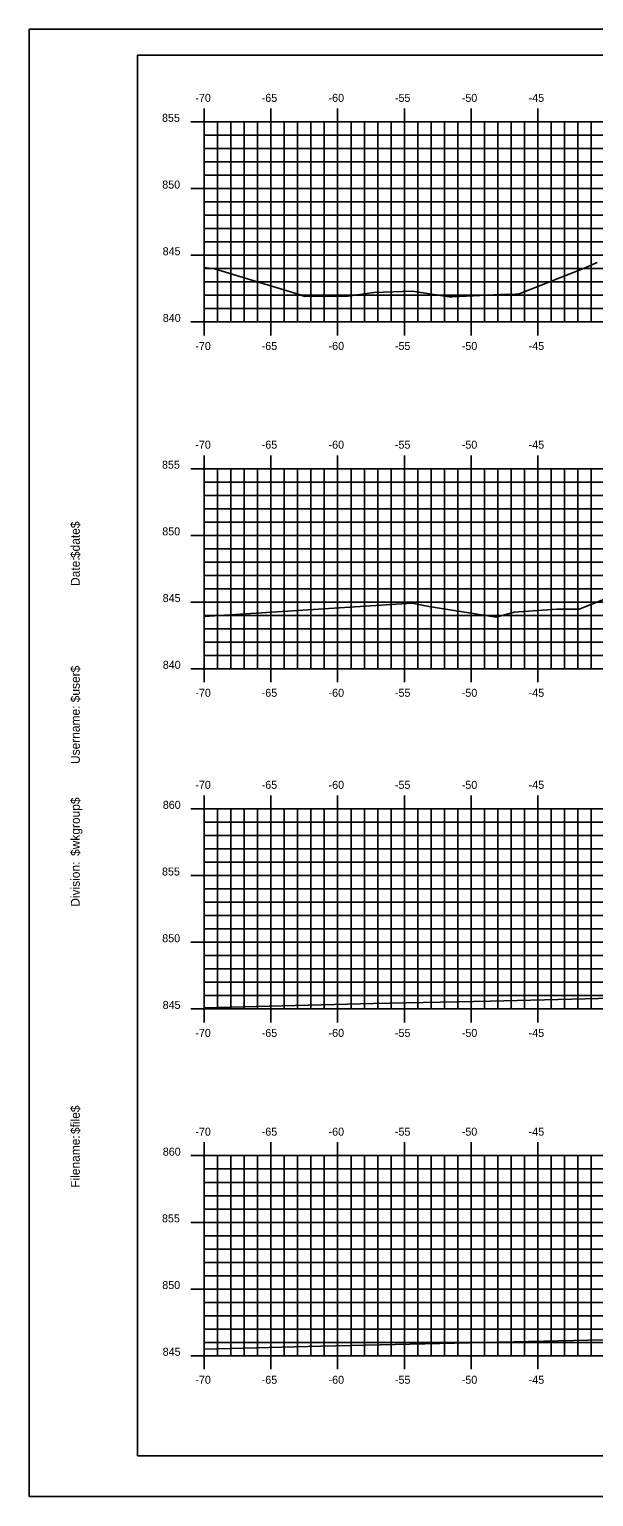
# Model space of a CAD drawing. Extents: x 2194004 to 2194525, y 863888 to 863998.
# Drawn here: x 2194171.9 to 2194214.2, y 863888.4 to 863998.4 of the extents above; entities that cross this region are included whole.
import ezdxf

# ---------------------------------------------------------------- set-up
doc = ezdxf.new("R2010")
doc.units = 0
for name, color, linetype in [('BORDER', 7, 'Continuous'), ('H_V ANNOTATION', 7, 'Continuous'), ('MAJOR', 7, 'Continuous'), ('MINOR', 7, 'Continuous'), ('PLOT BOUNDARY', 7, 'Continuous'), ('S_Roadway_Centerline', 7, 'Continuous')]:
    doc.layers.add(name, color=color, linetype=linetype)

msp = doc.modelspace()

# ---------------------------------------------------------------- linework, layer by layer
at = {"layer": 'BORDER'}
msp.add_lwpolyline([(2194179.99, 863891.45), (2194339.99, 863891.45), (2194339.99, 863996.45), (2194179.99, 863996.45)], close=True, dxfattribs=at)
at = {"layer": 'MAJOR'}
for p, q in [((2194184.99, 863992.45), (2194184.99, 863991.45)), ((2194189.99, 863992.45), (2194189.99, 863991.45)), ((2194194.99, 863992.45), (2194194.99, 863991.45)), ((2194199.99, 863992.45), (2194199.99, 863991.45)), ((2194204.99, 863992.45), (2194204.99, 863991.45)), ((2194209.99, 863992.45), (2194209.99, 863991.45)), ((2194183.98, 863991.45), (2194184.99, 863991.45)), ((2194184.99, 863991.45), (2194324.99, 863991.45)), ((2194184.99, 863976.45), (2194184.99, 863991.45)), ((2194184.99, 863976.45), (2194184.99, 863991.45)), ((2194189.99, 863976.45), (2194189.99, 863991.45)), ((2194194.99, 863976.45), (2194194.99, 863991.45)), ((2194199.99, 863976.45), (2194199.99, 863991.45)), ((2194204.99, 863976.45), (2194204.99, 863991.45)), ((2194209.99, 863976.45), (2194209.99, 863991.45)), ((2194183.98, 863986.45), (2194184.99, 863986.45)), ((2194184.99, 863986.45), (2194324.99, 863986.45)), ((2194183.98, 863981.45), (2194184.99, 863981.45)), ((2194184.99, 863981.45), (2194324.99, 863981.45)), ((2194183.98, 863976.45), (2194184.99, 863976.45)), ((2194184.99, 863976.45), (2194324.99, 863976.45)), ((2194184.99, 863975.44), (2194184.99, 863976.45)), ((2194189.99, 863975.44), (2194189.99, 863976.45)), ((2194194.99, 863975.44), (2194194.99, 863976.45)), ((2194199.99, 863975.44), (2194199.99, 863976.45)), ((2194204.99, 863975.44), (2194204.99, 863976.45)), ((2194209.99, 863975.44), (2194209.99, 863976.45)), ((2194184.99, 863966.45), (2194184.99, 863965.45)), ((2194189.99, 863966.45), (2194189.99, 863965.45)), ((2194194.99, 863966.45), (2194194.99, 863965.45)), ((2194199.99, 863966.45), (2194199.99, 863965.45)), ((2194204.99, 863966.45), (2194204.99, 863965.45)), ((2194209.99, 863966.45), (2194209.99, 863965.45)), ((2194183.98, 863965.45), (2194184.99, 863965.45)), ((2194184.99, 863965.45), (2194324.99, 863965.45)), ((2194184.99, 863950.45), (2194184.99, 863965.45)), ((2194184.99, 863950.45), (2194184.99, 863965.45)), ((2194189.99, 863950.45), (2194189.99, 863965.45)), ((2194194.99, 863950.45), (2194194.99, 863965.45)), ((2194199.99, 863950.45), (2194199.99, 863965.45)), ((2194204.99, 863950.45), (2194204.99, 863965.45)), ((2194209.99, 863950.45), (2194209.99, 863965.45)), ((2194183.98, 863960.45), (2194184.99, 863960.45)), ((2194184.99, 863960.45), (2194324.99, 863960.45)), ((2194183.98, 863955.45), (2194184.99, 863955.45)), ((2194184.99, 863955.45), (2194324.99, 863955.45)), ((2194183.98, 863950.45), (2194184.99, 863950.45)), ((2194184.99, 863950.45), (2194324.99, 863950.45)), ((2194184.99, 863949.44), (2194184.99, 863950.45)), ((2194189.99, 863949.44), (2194189.99, 863950.45)), ((2194194.99, 863949.44), (2194194.99, 863950.45)), ((2194199.99, 863949.44), (2194199.99, 863950.45)), ((2194204.99, 863949.44), (2194204.99, 863950.45)), ((2194209.99, 863949.44), (2194209.99, 863950.45)), ((2194184.99, 863940.95), (2194184.99, 863939.95)), ((2194189.99, 863940.95), (2194189.99, 863939.95)), ((2194194.99, 863940.95), (2194194.99, 863939.95)), ((2194199.99, 863940.95), (2194199.99, 863939.95)), ((2194204.99, 863940.95), (2194204.99, 863939.95)), ((2194209.99, 863940.95), (2194209.99, 863939.95)), ((2194183.98, 863939.95), (2194184.99, 863939.95)), ((2194184.99, 863939.95), (2194324.99, 863939.95)), ((2194184.99, 863939.95), (2194324.99, 863939.95)), ((2194184.99, 863924.95), (2194184.99, 863939.95)), ((2194184.99, 863924.95), (2194184.99, 863939.95)), ((2194189.99, 863924.95), (2194189.99, 863939.95)), ((2194194.99, 863924.95), (2194194.99, 863939.95)), ((2194199.99, 863924.95), (2194199.99, 863939.95)), ((2194204.99, 863924.95), (2194204.99, 863939.95)), ((2194209.99, 863924.95), (2194209.99, 863939.95)), ((2194183.98, 863934.95), (2194184.99, 863934.95)), ((2194184.99, 863934.95), (2194324.99, 863934.95)), ((2194183.98, 863929.95), (2194184.99, 863929.95)), ((2194184.99, 863929.95), (2194324.99, 863929.95)), ((2194183.98, 863924.95), (2194184.99, 863924.95)), ((2194184.99, 863924.95), (2194324.99, 863924.95)), ((2194184.99, 863923.94), (2194184.99, 863924.95)), ((2194189.99, 863923.94), (2194189.99, 863924.95)), ((2194194.99, 863923.94), (2194194.99, 863924.95)), ((2194199.99, 863923.94), (2194199.99, 863924.95)), ((2194204.99, 863923.94), (2194204.99, 863924.95)), ((2194209.99, 863923.94), (2194209.99, 863924.95)), ((2194184.99, 863914.95), (2194184.99, 863913.95)), ((2194189.99, 863914.95), (2194189.99, 863913.95)), ((2194194.99, 863914.95), (2194194.99, 863913.95)), ((2194199.99, 863914.95), (2194199.99, 863913.95)), ((2194204.99, 863914.95), (2194204.99, 863913.95)), ((2194209.99, 863914.95), (2194209.99, 863913.95)), ((2194183.98, 863913.95), (2194184.99, 863913.95)), ((2194184.99, 863913.95), (2194324.99, 863913.95)), ((2194184.99, 863913.95), (2194324.99, 863913.95)), ((2194184.99, 863898.95), (2194184.99, 863913.95)), ((2194184.99, 863898.95), (2194184.99, 863913.95)), ((2194189.99, 863898.95), (2194189.99, 863913.95)), ((2194194.99, 863898.95), (2194194.99, 863913.95)), ((2194199.99, 863898.95), (2194199.99, 863913.95)), ((2194204.99, 863898.95), (2194204.99, 863913.95)), ((2194209.99, 863898.95), (2194209.99, 863913.95)), ((2194183.98, 863908.95), (2194184.99, 863908.95)), ((2194184.99, 863908.95), (2194324.99, 863908.95)), ((2194183.98, 863903.95), (2194184.99, 863903.95)), ((2194184.99, 863903.95), (2194324.99, 863903.95)), ((2194183.98, 863898.95), (2194184.99, 863898.95)), ((2194184.99, 863898.95), (2194324.99, 863898.95)), ((2194184.99, 863897.94), (2194184.99, 863898.95)), ((2194189.99, 863897.94), (2194189.99, 863898.95)), ((2194194.99, 863897.94), (2194194.99, 863898.95)), ((2194199.99, 863897.94), (2194199.99, 863898.95)), ((2194204.99, 863897.94), (2194204.99, 863898.95)), ((2194209.99, 863897.94), (2194209.99, 863898.95))]:
    msp.add_line(p, q, dxfattribs=at)
at = {"layer": 'MINOR'}
for p, q in [((2194185.99, 863976.45), (2194185.99, 863991.45)), ((2194186.99, 863976.45), (2194186.99, 863991.45)), ((2194187.99, 863976.45), (2194187.99, 863991.45)), ((2194188.99, 863976.45), (2194188.99, 863991.45)), ((2194190.99, 863976.45), (2194190.99, 863991.45)), ((2194191.99, 863976.45), (2194191.99, 863991.45)), ((2194192.99, 863976.45), (2194192.99, 863991.45)), ((2194193.99, 863976.45), (2194193.99, 863991.45)), ((2194195.99, 863976.45), (2194195.99, 863991.45)), ((2194196.99, 863976.45), (2194196.99, 863991.45)), ((2194197.99, 863976.45), (2194197.99, 863991.45)), ((2194198.99, 863976.45), (2194198.99, 863991.45)), ((2194200.99, 863976.45), (2194200.99, 863991.45)), ((2194201.99, 863976.45), (2194201.99, 863991.45)), ((2194202.99, 863976.45), (2194202.99, 863991.45)), ((2194203.99, 863976.45), (2194203.99, 863991.45)), ((2194205.99, 863976.45), (2194205.99, 863991.45)), ((2194206.99, 863976.45), (2194206.99, 863991.45)), ((2194207.99, 863976.45), (2194207.99, 863991.45)), ((2194208.99, 863976.45), (2194208.99, 863991.45)), ((2194210.99, 863976.45), (2194210.99, 863991.45)), ((2194211.99, 863976.45), (2194211.99, 863991.45)), ((2194212.99, 863976.45), (2194212.99, 863991.45)), ((2194213.99, 863976.45), (2194213.99, 863991.45)), ((2194184.99, 863990.45), (2194324.99, 863990.45)), ((2194184.99, 863990.45), (2194185.99, 863990.45)), ((2194184.99, 863989.45), (2194324.99, 863989.45)), ((2194184.99, 863989.45), (2194185.99, 863989.45)), ((2194184.99, 863988.45), (2194324.99, 863988.45)), ((2194184.99, 863988.45), (2194185.99, 863988.45)), ((2194184.99, 863987.45), (2194324.99, 863987.45)), ((2194184.99, 863987.45), (2194185.99, 863987.45)), ((2194184.99, 863985.45), (2194324.99, 863985.45)), ((2194184.99, 863985.45), (2194185.99, 863985.45)), ((2194184.99, 863984.45), (2194324.99, 863984.45)), ((2194184.99, 863984.45), (2194185.99, 863984.45)), ((2194184.99, 863983.45), (2194324.99, 863983.45)), ((2194184.99, 863983.45), (2194185.99, 863983.45)), ((2194184.99, 863982.45), (2194324.99, 863982.45)), ((2194184.99, 863982.45), (2194185.99, 863982.45)), ((2194184.99, 863980.45), (2194324.99, 863980.45)), ((2194184.99, 863980.45), (2194185.99, 863980.45)), ((2194184.99, 863979.45), (2194324.99, 863979.45)), ((2194184.99, 863979.45), (2194185.99, 863979.45)), ((2194184.99, 863978.45), (2194324.99, 863978.45)), ((2194184.99, 863978.45), (2194185.99, 863978.45)), ((2194184.99, 863977.45), (2194324.99, 863977.45)), ((2194184.99, 863977.45), (2194185.99, 863977.45)), ((2194185.99, 863950.45), (2194185.99, 863965.45)), ((2194186.99, 863950.45), (2194186.99, 863965.45)), ((2194187.99, 863950.45), (2194187.99, 863965.45)), ((2194188.99, 863950.45), (2194188.99, 863965.45)), ((2194190.99, 863950.45), (2194190.99, 863965.45)), ((2194191.99, 863950.45), (2194191.99, 863965.45)), ((2194192.99, 863950.45), (2194192.99, 863965.45)), ((2194193.99, 863950.45), (2194193.99, 863965.45)), ((2194195.99, 863950.45), (2194195.99, 863965.45)), ((2194196.99, 863950.45), (2194196.99, 863965.45)), ((2194197.99, 863950.45), (2194197.99, 863965.45)), ((2194198.99, 863950.45), (2194198.99, 863965.45)), ((2194200.99, 863950.45), (2194200.99, 863965.45)), ((2194201.99, 863950.45), (2194201.99, 863965.45)), ((2194202.99, 863950.45), (2194202.99, 863965.45)), ((2194203.99, 863950.45), (2194203.99, 863965.45)), ((2194205.99, 863950.45), (2194205.99, 863965.45)), ((2194206.99, 863950.45), (2194206.99, 863965.45)), ((2194207.99, 863950.45), (2194207.99, 863965.45)), ((2194208.99, 863950.45), (2194208.99, 863965.45)), ((2194210.99, 863950.45), (2194210.99, 863965.45)), ((2194211.99, 863950.45), (2194211.99, 863965.45)), ((2194212.99, 863950.45), (2194212.99, 863965.45)), ((2194213.99, 863950.45), (2194213.99, 863965.45)), ((2194184.99, 863964.45), (2194324.99, 863964.45)), ((2194184.99, 863964.45), (2194185.99, 863964.45)), ((2194184.99, 863963.45), (2194324.99, 863963.45)), ((2194184.99, 863963.45), (2194185.99, 863963.45)), ((2194184.99, 863962.45), (2194324.99, 863962.45)), ((2194184.99, 863962.45), (2194185.99, 863962.45)), ((2194184.99, 863961.45), (2194324.99, 863961.45)), ((2194184.99, 863961.45), (2194185.99, 863961.45)), ((2194184.99, 863959.45), (2194324.99, 863959.45)), ((2194184.99, 863959.45), (2194185.99, 863959.45)), ((2194184.99, 863958.45), (2194324.99, 863958.45)), ((2194184.99, 863958.45), (2194185.99, 863958.45)), ((2194184.99, 863957.45), (2194324.99, 863957.45)), ((2194184.99, 863957.45), (2194185.99, 863957.45)), ((2194184.99, 863956.45), (2194324.99, 863956.45)), ((2194184.99, 863956.45), (2194185.99, 863956.45)), ((2194184.99, 863954.45), (2194324.99, 863954.45)), ((2194184.99, 863954.45), (2194185.99, 863954.45)), ((2194184.99, 863953.45), (2194324.99, 863953.45)), ((2194184.99, 863953.45), (2194185.99, 863953.45)), ((2194184.99, 863952.45), (2194324.99, 863952.45)), ((2194184.99, 863952.45), (2194185.99, 863952.45)), ((2194184.99, 863951.45), (2194324.99, 863951.45)), ((2194184.99, 863951.45), (2194185.99, 863951.45)), ((2194184.99, 863938.95), (2194324.99, 863938.95)), ((2194184.99, 863938.95), (2194185.99, 863938.95)), ((2194185.99, 863924.95), (2194185.99, 863939.95)), ((2194186.99, 863924.95), (2194186.99, 863939.95)), ((2194187.99, 863924.95), (2194187.99, 863939.95)), ((2194188.99, 863924.95), (2194188.99, 863939.95)), ((2194190.99, 863924.95), (2194190.99, 863939.95)), ((2194191.99, 863924.95), (2194191.99, 863939.95)), ((2194192.99, 863924.95), (2194192.99, 863939.95)), ((2194193.99, 863924.95), (2194193.99, 863939.95)), ((2194195.99, 863924.95), (2194195.99, 863939.95)), ((2194196.99, 863924.95), (2194196.99, 863939.95)), ((2194197.99, 863924.95), (2194197.99, 863939.95)), ((2194198.99, 863924.95), (2194198.99, 863939.95)), ((2194200.99, 863924.95), (2194200.99, 863939.95)), ((2194201.99, 863924.95), (2194201.99, 863939.95)), ((2194202.99, 863924.95), (2194202.99, 863939.95)), ((2194203.99, 863924.95), (2194203.99, 863939.95)), ((2194205.99, 863924.95), (2194205.99, 863939.95)), ((2194206.99, 863924.95), (2194206.99, 863939.95)), ((2194207.99, 863924.95), (2194207.99, 863939.95)), ((2194208.99, 863924.95), (2194208.99, 863939.95)), ((2194210.99, 863924.95), (2194210.99, 863939.95)), ((2194211.99, 863924.95), (2194211.99, 863939.95)), ((2194212.99, 863924.95), (2194212.99, 863939.95)), ((2194213.99, 863924.95), (2194213.99, 863939.95)), ((2194184.99, 863937.95), (2194324.99, 863937.95)), ((2194184.99, 863937.95), (2194185.99, 863937.95)), ((2194184.99, 863936.95), (2194324.99, 863936.95)), ((2194184.99, 863936.95), (2194185.99, 863936.95)), ((2194184.99, 863935.95), (2194324.99, 863935.95)), ((2194184.99, 863935.95), (2194185.99, 863935.95)), ((2194184.99, 863933.95), (2194324.99, 863933.95)), ((2194184.99, 863933.95), (2194185.99, 863933.95)), ((2194184.99, 863932.95), (2194324.99, 863932.95)), ((2194184.99, 863932.95), (2194185.99, 863932.95)), ((2194184.99, 863931.95), (2194324.99, 863931.95)), ((2194184.99, 863931.95), (2194185.99, 863931.95)), ((2194184.99, 863930.95), (2194324.99, 863930.95)), ((2194184.99, 863930.95), (2194185.99, 863930.95)), ((2194184.99, 863928.95), (2194324.99, 863928.95)), ((2194184.99, 863928.95), (2194185.99, 863928.95)), ((2194184.99, 863927.95), (2194324.99, 863927.95)), ((2194184.99, 863927.95), (2194185.99, 863927.95)), ((2194184.99, 863926.95), (2194324.99, 863926.95)), ((2194184.99, 863926.95), (2194185.99, 863926.95)), ((2194184.99, 863925.95), (2194324.99, 863925.95)), ((2194184.99, 863925.95), (2194185.99, 863925.95)), ((2194185.99, 863898.95), (2194185.99, 863913.95)), ((2194186.99, 863898.95), (2194186.99, 863913.95)), ((2194187.99, 863898.95), (2194187.99, 863913.95)), ((2194188.99, 863898.95), (2194188.99, 863913.95)), ((2194190.99, 863898.95), (2194190.99, 863913.95)), ((2194191.99, 863898.95), (2194191.99, 863913.95)), ((2194192.99, 863898.95), (2194192.99, 863913.95)), ((2194193.99, 863898.95), (2194193.99, 863913.95)), ((2194195.99, 863898.95), (2194195.99, 863913.95)), ((2194196.99, 863898.95), (2194196.99, 863913.95)), ((2194197.99, 863898.95), (2194197.99, 863913.95)), ((2194198.99, 863898.95), (2194198.99, 863913.95)), ((2194200.99, 863898.95), (2194200.99, 863913.95)), ((2194201.99, 863898.95), (2194201.99, 863913.95)), ((2194202.99, 863898.95), (2194202.99, 863913.95)), ((2194203.99, 863898.95), (2194203.99, 863913.95)), ((2194205.99, 863898.95), (2194205.99, 863913.95)), ((2194206.99, 863898.95), (2194206.99, 863913.95)), ((2194207.99, 863898.95), (2194207.99, 863913.95)), ((2194208.99, 863898.95), (2194208.99, 863913.95)), ((2194210.99, 863898.95), (2194210.99, 863913.95)), ((2194211.99, 863898.95), (2194211.99, 863913.95)), ((2194212.99, 863898.95), (2194212.99, 863913.95)), ((2194213.99, 863898.95), (2194213.99, 863913.95)), ((2194184.99, 863912.95), (2194324.99, 863912.95)), ((2194184.99, 863912.95), (2194185.99, 863912.95)), ((2194184.99, 863911.95), (2194324.99, 863911.95)), ((2194184.99, 863911.95), (2194185.99, 863911.95)), ((2194184.99, 863910.95), (2194324.99, 863910.95)), ((2194184.99, 863910.95), (2194185.99, 863910.95)), ((2194184.99, 863909.95), (2194324.99, 863909.95)), ((2194184.99, 863909.95), (2194185.99, 863909.95)), ((2194184.99, 863907.95), (2194324.99, 863907.95)), ((2194184.99, 863907.95), (2194185.99, 863907.95)), ((2194184.99, 863906.95), (2194324.99, 863906.95)), ((2194184.99, 863906.95), (2194185.99, 863906.95)), ((2194184.99, 863905.95), (2194324.99, 863905.95)), ((2194184.99, 863905.95), (2194185.99, 863905.95)), ((2194184.99, 863904.95), (2194324.99, 863904.95)), ((2194184.99, 863904.95), (2194185.99, 863904.95)), ((2194184.99, 863902.95), (2194324.99, 863902.95)), ((2194184.99, 863902.95), (2194185.99, 863902.95)), ((2194184.99, 863901.95), (2194324.99, 863901.95)), ((2194184.99, 863901.95), (2194185.99, 863901.95)), ((2194184.99, 863900.95), (2194324.99, 863900.95)), ((2194184.99, 863900.95), (2194185.99, 863900.95)), ((2194184.99, 863899.95), (2194324.99, 863899.95)), ((2194184.99, 863899.95), (2194185.99, 863899.95))]:
    msp.add_line(p, q, dxfattribs=at)
at = {"layer": 'PLOT BOUNDARY'}
msp.add_lwpolyline([(2194171.89, 863888.39), (2194341.89, 863888.39), (2194341.89, 863998.39), (2194171.89, 863998.39)], close=True, dxfattribs=at)
at = {"layer": 'S_Roadway_Centerline'}
for points in [[(2194184.99, 863980.53), (2194185.76, 863980.43), (2194192.02, 863978.54), (2194192.54, 863978.37), (2194195.76, 863978.39), (2194197.71, 863978.66), (2194200.57, 863978.76), (2194203.35, 863978.34), (2194203.57, 863978.33), (2194207.22, 863978.51), (2194208.07, 863978.51), (2194208.59, 863978.55), (2194213.42, 863980.46), (2194214.43, 863980.92)], [(2194184.99, 863954.36), (2194200.57, 863955.36), (2194201.83, 863955.13), (2194206.87, 863954.31), (2194208.21, 863954.7), (2194211.4, 863954.92), (2194213.08, 863954.93), (2194215.55, 863955.9), (2194228.25, 863960.36), (2194233.48, 863960.84), (2194239.44, 863961.24), (2194243.19, 863961.37), (2194243.42, 863961.4), (2194254.11, 863961.5), (2194254.96, 863961.51), (2194255.83, 863961.51), (2194266.22, 863961.53), (2194266.62, 863961.51), (2194272.97, 863961.18), (2194273.83, 863960.94), (2194274.78, 863960.56), (2194281.74, 863958.17), (2194283.1, 863958.17)], [(2194184.99, 863925.02), (2194197.64, 863925.35), (2194206.42, 863925.54), (2194218.59, 863925.82), (2194219.35, 863925.91), (2194232.66, 863930.45), (2194232.83, 863930.51), (2194232.96, 863930.52), (2194238.59, 863931.16), (2194241.16, 863931.24), (2194243.34, 863931.37), (2194250.98, 863931.44), (2194254.95, 863931.51), (2194262.37, 863931.53), (2194266.28, 863931.5), (2194268.39, 863931.48), (2194272.75, 863931.25), (2194275.86, 863931.1), (2194280.9, 863928.61), (2194281.52, 863928.4), (2194284.11, 863928.41)], [(2194184.99, 863899.44), (2194193.74, 863899.67), (2194220.46, 863900.26), (2194220.78, 863900.27), (2194220.83, 863900.27), (2194220.89, 863900.28), (2194220.89, 863900.28), (2194233.8, 863904.69), (2194234, 863904.73), (2194238.54, 863905.24), (2194240.57, 863905.31), (2194243.32, 863905.47), (2194249.92, 863905.53), (2194254.95, 863905.62), (2194261.36, 863905.63), (2194266.29, 863905.6), (2194268.97, 863905.57), (2194272.65, 863905.38), (2194276.66, 863905.18), (2194281.44, 863902.83), (2194282.09, 863902.5), (2194284.53, 863902.51)]]:
    msp.add_lwpolyline(points, dxfattribs=at)

# ---------------------------------------------------------------- texts
at = {"layer": 'BORDER'}
for s, p in [('$date$', (2194175.67, 863958.75)), ('Date:', (2194175.67, 863956.66)), ('$user$', (2194175.67, 863947.94)), ('Username:', (2194175.67, 863943.31)), ('$wkgroup$', (2194175.67, 863936.42)), ('Division:', (2194175.67, 863932.61)), ('$file$', (2194175.67, 863915.57)), ('Filename:', (2194175.67, 863911.54))]:
    msp.add_text(s, height=0.67, rotation=90, dxfattribs=at).set_placement(p)
at = {"layer": 'H_V ANNOTATION'}
for s, p in [('-70', (2194184.33, 863992.95)), ('-65', (2194189.3, 863992.95)), ('-60', (2194194.31, 863992.95)), ('-55', (2194199.28, 863992.95)), ('-50', (2194204.29, 863992.95)), ('-45', (2194209.3, 863992.95)), ('855', (2194181.83, 863991.45)), ('850', (2194181.85, 863986.45)), ('845', (2194181.88, 863981.45)), ('840', (2194181.89, 863976.45)), ('-70', (2194184.33, 863974.35)), ('-65', (2194189.3, 863974.35)), ('-60', (2194194.31, 863974.35)), ('-55', (2194199.28, 863974.35)), ('-50', (2194204.29, 863974.35)), ('-45', (2194209.3, 863974.35)), ('-70', (2194184.33, 863966.95)), ('-65', (2194189.3, 863966.95)), ('-60', (2194194.31, 863966.95)), ('-55', (2194199.28, 863966.95)), ('-50', (2194204.29, 863966.95)), ('-45', (2194209.3, 863966.95)), ('855', (2194181.83, 863965.45)), ('850', (2194181.85, 863960.45)), ('845', (2194181.88, 863955.45)), ('840', (2194181.89, 863950.45)), ('-70', (2194184.33, 863948.35)), ('-65', (2194189.3, 863948.35)), ('-60', (2194194.31, 863948.35)), ('-55', (2194199.28, 863948.35)), ('-50', (2194204.29, 863948.35)), ('-45', (2194209.3, 863948.35)), ('-70', (2194184.33, 863941.45)), ('-65', (2194189.3, 863941.45)), ('-60', (2194194.31, 863941.45)), ('-55', (2194199.28, 863941.45)), ('-50', (2194204.29, 863941.45)), ('-45', (2194209.3, 863941.45)), ('860', (2194181.89, 863939.95)), ('855', (2194181.83, 863934.95)), ('850', (2194181.85, 863929.95)), ('845', (2194181.88, 863924.95)), ('-70', (2194184.33, 863922.85)), ('-65', (2194189.3, 863922.85)), ('-60', (2194194.31, 863922.85)), ('-55', (2194199.28, 863922.85)), ('-50', (2194204.29, 863922.85)), ('-45', (2194209.3, 863922.85)), ('-70', (2194184.33, 863915.45)), ('-65', (2194189.3, 863915.45)), ('-60', (2194194.31, 863915.45)), ('-55', (2194199.28, 863915.45)), ('-50', (2194204.29, 863915.45)), ('-45', (2194209.3, 863915.45)), ('860', (2194181.89, 863913.95)), ('855', (2194181.83, 863908.95)), ('850', (2194181.85, 863903.95)), ('845', (2194181.88, 863898.95)), ('-70', (2194184.33, 863896.85)), ('-65', (2194189.3, 863896.85)), ('-60', (2194194.31, 863896.85)), ('-55', (2194199.28, 863896.85)), ('-50', (2194204.29, 863896.85)), ('-45', (2194209.3, 863896.85))]:
    msp.add_text(s, height=0.6, dxfattribs=at).set_placement(p)

doc.saveas('drawing.dxf')
